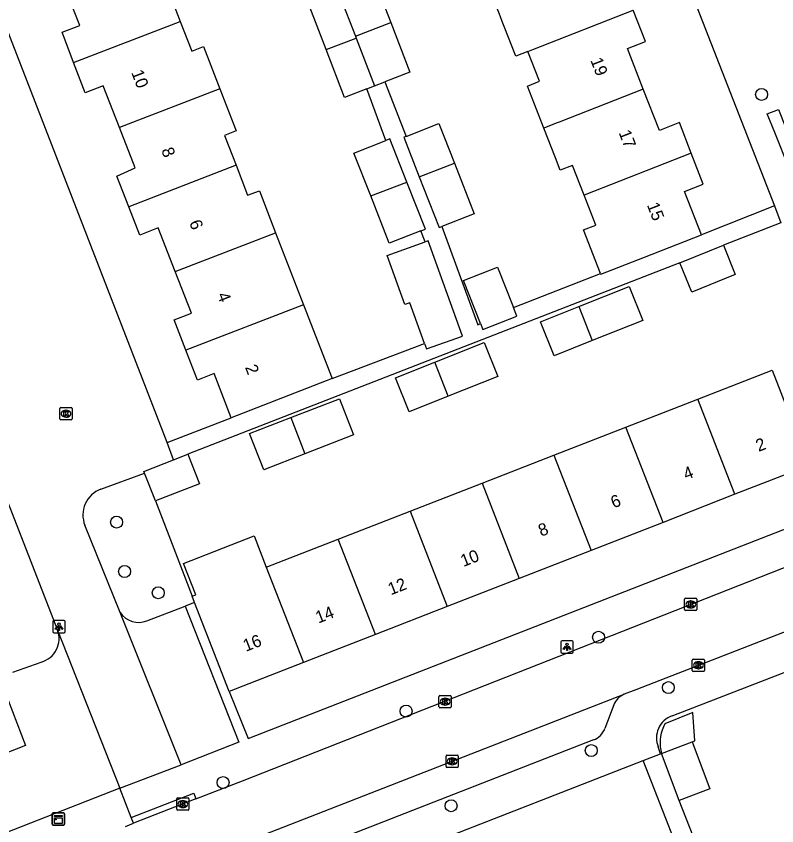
# Model space of a CAD drawing. Extents: x 159689 to 160786, y 387323 to 388339.
# Drawn here: x 160207.9 to 160270, y 387538.8 to 387604.9 of the extents above; entities that cross this region are included whole.
import ezdxf

# ---------------------------------------------------------------- set-up
doc = ezdxf.new("R2010")
doc.units = 0
for name, color, linetype in [('IMGEO_Boom', 7, 'Continuous'), ('IMGEO_Groenvoorziening', 7, 'Continuous'), ('IMGEO_Kast', 7, 'Continuous'), ('IMGEO_Kolk', 7, 'Continuous'), ('IMGEO_Lichtpunt', 7, 'Continuous'), ('IMGEO_Pand', 7, 'Continuous'), ('IMGEO_Pand_nummerreeks', 7, 'Continuous'), ('IMGEO_Parkeervlak_open', 7, 'Continuous'), ('IMGEO_Rijbaan_lokaal_open', 7, 'Continuous'), ('IMGEO_Voetpad_open', 7, 'Continuous')]:
    doc.layers.add(name, color=color, linetype=linetype)

msp = doc.modelspace()

# ---------------------------------------------------------------- linework, layer by layer
at = {"layer": 'IMGEO_Boom'}
for centre in [(160268.735, 387598.473), (160216.098, 387563.567), (160216.751, 387559.535), (160219.498, 387557.799), (160255.428, 387554.165), (160261.122, 387550.056), (160239.725, 387548.138), (160254.834, 387544.919), (160224.786, 387542.31), (160243.394, 387540.419)]:
    msp.add_circle(centre, 0.489, dxfattribs=at)
at = {"layer": 'IMGEO_Groenvoorziening'}
msp.add_lwpolyline([(160219.269, 387565.292), (160222.251, 387557.517)], dxfattribs=at)
at = {"layer": 'IMGEO_Kast'}
for p, q in [((160210.922, 387539.827), (160211.763, 387539.827)), ((160211.763, 387539.827), (160210.922, 387539.827)), ((160210.847, 387538.902), (160210.847, 387539.743)), ((160210.847, 387539.743), (160210.847, 387538.902)), ((160211.847, 387539.752), (160211.847, 387538.911)), ((160211.847, 387538.911), (160211.847, 387539.752)), ((160211.772, 387538.827), (160210.931, 387538.827)), ((160210.931, 387538.827), (160211.772, 387538.827))]:
    msp.add_line(p, q, dxfattribs=at)
for points in [[(160211.042, 387539.617), (160211.642, 387539.617), (160211.642, 387539.532), (160211.042, 387539.532), (160211.042, 387539.617)], [(160211.042, 387539.442), (160211.642, 387539.442), (160211.642, 387538.953), (160211.042, 387538.953), (160211.042, 387539.442)]]:
    msp.add_lwpolyline(points, dxfattribs=at)
msp.add_circle((160211.126, 387539.291), 0.0377, dxfattribs=at)
for centre, start, end in [((160210.925, 387539.749), 92.4484, 184.28452), ((160210.925, 387539.749), 92.4484, 184.28452), ((160211.769, 387539.749), 2.4484, 94.28452), ((160211.769, 387539.749), 2.4484, 94.28452), ((160210.925, 387538.905), 182.4484, 274.28452), ((160210.925, 387538.905), 182.4484, 274.28452), ((160211.769, 387538.905), 272.4484, 4.28452), ((160211.769, 387538.905), 272.4484, 4.28452)]:
    msp.add_arc(centre, 0.0779, start, end, dxfattribs=at)
at = {"layer": 'IMGEO_Kolk'}
for p, q in [((160211.54, 387572.916), (160212.392, 387572.916)), ((160211.465, 387571.99), (160211.465, 387572.842)), ((160211.953, 387572.696), (160211.978, 387572.696)), ((160212.466, 387572.842), (160212.466, 387571.99)), ((160212.392, 387571.916), (160211.54, 387571.916)), ((160211.976, 387572.136), (160211.951, 387572.136)), ((160262.451, 387556.425), (160262.451, 387557.277)), ((160262.526, 387557.351), (160263.378, 387557.351)), ((160262.939, 387557.131), (160262.964, 387557.131)), ((160263.452, 387557.277), (160263.452, 387556.425)), ((160263.378, 387556.351), (160262.526, 387556.351)), ((160262.962, 387556.571), (160262.937, 387556.571)), ((160263.153, 387552.381), (160264.005, 387552.381)), ((160263.078, 387551.455), (160263.078, 387552.307)), ((160263.566, 387552.161), (160263.591, 387552.161)), ((160264.079, 387552.307), (160264.079, 387551.455)), ((160264.005, 387551.381), (160263.153, 387551.381)), ((160263.589, 387551.601), (160263.564, 387551.601)), ((160242.406, 387548.483), (160242.406, 387549.335)), ((160242.481, 387549.409), (160243.333, 387549.409)), ((160242.894, 387549.189), (160242.919, 387549.189)), ((160243.407, 387549.335), (160243.407, 387548.483)), ((160243.333, 387548.409), (160242.481, 387548.409)), ((160242.917, 387548.629), (160242.892, 387548.629)), ((160242.978, 387543.615), (160242.978, 387544.467)), ((160243.053, 387544.541), (160243.905, 387544.541)), ((160243.979, 387544.467), (160243.979, 387543.615)), ((160243.466, 387544.321), (160243.491, 387544.321)), ((160243.905, 387543.541), (160243.053, 387543.541)), ((160243.489, 387543.761), (160243.464, 387543.761)), ((160221.001, 387540.128), (160221.001, 387540.98)), ((160221.076, 387541.054), (160221.928, 387541.054)), ((160221.489, 387540.834), (160221.514, 387540.834)), ((160222.002, 387540.98), (160222.002, 387540.128)), ((160221.928, 387540.054), (160221.076, 387540.054)), ((160221.512, 387540.274), (160221.487, 387540.274))]:
    msp.add_line(p, q, dxfattribs=at)
for points in [[(160211.54, 387572.916), (160212.392, 387572.916)], [(160211.465, 387571.99), (160211.465, 387572.842)], [(160211.786, 387572.616), (160211.909, 387572.616), (160211.909, 387572.465), (160212.039, 387572.616), (160212.203, 387572.616), (160212.057, 387572.465), (160212.21, 387572.216), (160212.058, 387572.216), (160211.973, 387572.38), (160211.909, 387572.313), (160211.909, 387572.216), (160211.786, 387572.216), (160211.786, 387572.616)], [(160212.466, 387572.842), (160212.466, 387571.99)], [(160212.392, 387571.916), (160211.54, 387571.916)], [(160262.451, 387556.425), (160262.451, 387557.277)], [(160262.526, 387557.351), (160263.378, 387557.351)], [(160262.772, 387557.051), (160262.895, 387557.051), (160262.895, 387556.9), (160263.025, 387557.051), (160263.189, 387557.051), (160263.043, 387556.9), (160263.196, 387556.651), (160263.044, 387556.651), (160262.959, 387556.815), (160262.895, 387556.748), (160262.895, 387556.651), (160262.772, 387556.651), (160262.772, 387557.051)], [(160263.452, 387557.277), (160263.452, 387556.425)], [(160263.378, 387556.351), (160262.526, 387556.351)], [(160263.153, 387552.381), (160264.005, 387552.381)], [(160263.078, 387551.455), (160263.078, 387552.307)], [(160263.399, 387552.081), (160263.522, 387552.081), (160263.522, 387551.93), (160263.652, 387552.081), (160263.816, 387552.081), (160263.67, 387551.93), (160263.823, 387551.681), (160263.671, 387551.681), (160263.586, 387551.845), (160263.522, 387551.778), (160263.522, 387551.681), (160263.399, 387551.681), (160263.399, 387552.081)], [(160264.079, 387552.307), (160264.079, 387551.455)], [(160264.005, 387551.381), (160263.153, 387551.381)], [(160242.406, 387548.483), (160242.406, 387549.335)], [(160242.481, 387549.409), (160243.333, 387549.409)], [(160242.727, 387549.109), (160242.85, 387549.109), (160242.85, 387548.958), (160242.98, 387549.109), (160243.144, 387549.109), (160242.998, 387548.958), (160243.151, 387548.709), (160242.999, 387548.709), (160242.914, 387548.873), (160242.85, 387548.806), (160242.85, 387548.709), (160242.727, 387548.709), (160242.727, 387549.109)], [(160243.407, 387549.335), (160243.407, 387548.483)], [(160243.333, 387548.409), (160242.481, 387548.409)], [(160242.978, 387543.615), (160242.978, 387544.467)], [(160243.053, 387544.541), (160243.905, 387544.541)], [(160243.979, 387544.467), (160243.979, 387543.615)], [(160243.299, 387544.241), (160243.422, 387544.241), (160243.422, 387544.09), (160243.552, 387544.241), (160243.716, 387544.241), (160243.57, 387544.09), (160243.723, 387543.841), (160243.571, 387543.841), (160243.486, 387544.005), (160243.422, 387543.938), (160243.422, 387543.841), (160243.299, 387543.841), (160243.299, 387544.241)], [(160243.905, 387543.541), (160243.053, 387543.541)], [(160221.001, 387540.128), (160221.001, 387540.98)], [(160221.076, 387541.054), (160221.928, 387541.054)], [(160221.322, 387540.754), (160221.445, 387540.754), (160221.445, 387540.603), (160221.575, 387540.754), (160221.739, 387540.754), (160221.593, 387540.603), (160221.746, 387540.354), (160221.594, 387540.354), (160221.509, 387540.518), (160221.445, 387540.451), (160221.445, 387540.354), (160221.322, 387540.354), (160221.322, 387540.754)], [(160222.002, 387540.98), (160222.002, 387540.128)], [(160221.928, 387540.054), (160221.076, 387540.054)]]:
    msp.add_lwpolyline(points, dxfattribs=at)
for centre, start, end in [((160211.542, 387572.84), 91.55205, 178.44795), ((160211.542, 387572.84), 91.55205, 178.44795), ((160212.39, 387572.84), 1.55205, 88.44795), ((160212.39, 387572.84), 1.55205, 88.44795), ((160211.542, 387571.992), 181.55205, 268.44795), ((160211.542, 387571.992), 181.55205, 268.44795), ((160212.39, 387571.992), 271.55205, 358.44795), ((160212.39, 387571.992), 271.55205, 358.44795), ((160262.528, 387557.275), 91.55205, 178.44795), ((160262.528, 387557.275), 91.55205, 178.44795), ((160263.376, 387557.275), 1.55205, 88.44795), ((160263.376, 387557.275), 1.55205, 88.44795), ((160262.528, 387556.427), 181.55205, 268.44795), ((160262.528, 387556.427), 181.55205, 268.44795), ((160263.376, 387556.427), 271.55205, 358.44795), ((160263.376, 387556.427), 271.55205, 358.44795), ((160263.155, 387552.305), 91.55205, 178.44795), ((160263.155, 387552.305), 91.55205, 178.44795), ((160264.003, 387552.305), 1.55205, 88.44795), ((160264.003, 387552.305), 1.55205, 88.44795), ((160263.155, 387551.457), 181.55205, 268.44795), ((160263.155, 387551.457), 181.55205, 268.44795), ((160264.003, 387551.457), 271.55205, 358.44795), ((160264.003, 387551.457), 271.55205, 358.44795), ((160242.483, 387549.333), 91.55205, 178.44795), ((160242.483, 387549.333), 91.55205, 178.44795), ((160243.331, 387549.333), 1.55205, 88.44795), ((160243.331, 387549.333), 1.55205, 88.44795), ((160242.483, 387548.485), 181.55205, 268.44795), ((160242.483, 387548.485), 181.55205, 268.44795), ((160243.331, 387548.485), 271.55205, 358.44795), ((160243.331, 387548.485), 271.55205, 358.44795), ((160243.055, 387544.465), 91.55205, 178.44795), ((160243.055, 387544.465), 91.55205, 178.44795), ((160243.903, 387544.465), 1.55205, 88.44795), ((160243.903, 387544.465), 1.55205, 88.44795), ((160243.055, 387543.617), 181.55205, 268.44795), ((160243.055, 387543.617), 181.55205, 268.44795), ((160243.903, 387543.617), 271.55205, 358.44795), ((160243.903, 387543.617), 271.55205, 358.44795), ((160221.078, 387540.978), 91.55205, 178.44795), ((160221.078, 387540.978), 91.55205, 178.44795), ((160221.926, 387540.978), 1.55205, 88.44795), ((160221.926, 387540.978), 1.55205, 88.44795), ((160221.078, 387540.13), 181.55205, 268.44795), ((160221.078, 387540.13), 181.55205, 268.44795), ((160221.926, 387540.13), 271.55205, 358.44795), ((160221.926, 387540.13), 271.55205, 358.44795)]:
    msp.add_arc(centre, 0.0765, start, end, dxfattribs=at)
for centre, major_axis, ratio, start_param, end_param in [((160211.952, 387572.416), (-0.387, 0.002), 0.722429, 4.712389, 7.853982), ((160211.977, 387572.416), (-0.39, 0.002), 0.717154, 1.570796, 4.712389), ((160262.938, 387556.851), (-0.387, 0.002), 0.722429, 4.712389, 7.853982), ((160262.963, 387556.851), (-0.39, 0.002), 0.717154, 1.570796, 4.712389), ((160263.565, 387551.881), (-0.387, 0.002), 0.722429, 4.712389, 7.853982), ((160263.59, 387551.881), (-0.39, 0.002), 0.717154, 1.570796, 4.712389), ((160242.893, 387548.909), (-0.387, 0.002), 0.722429, 4.712389, 7.853982), ((160242.918, 387548.909), (-0.39, 0.002), 0.717154, 1.570796, 4.712389), ((160243.465, 387544.041), (-0.387, 0.002), 0.722429, 4.712389, 7.853982), ((160243.49, 387544.041), (-0.39, 0.002), 0.717154, 1.570796, 4.712389), ((160221.488, 387540.554), (-0.387, 0.002), 0.722429, 4.712389, 7.853982), ((160221.513, 387540.554), (-0.39, 0.002), 0.717154, 1.570796, 4.712389)]:
    msp.add_ellipse(centre, major_axis=major_axis, ratio=ratio, start_param=start_param, end_param=end_param, dxfattribs=at)
at = {"layer": 'IMGEO_Lichtpunt'}
for p, q in [((160210.906, 387555.438), (160210.906, 387554.631)), ((160210.906, 387555.438), (160210.906, 387554.631)), ((160211.808, 387555.533), (160211, 387555.533)), ((160211.808, 387555.533), (160211, 387555.533)), ((160211.902, 387554.631), (160211.902, 387555.438)), ((160211.902, 387554.631), (160211.902, 387555.438)), ((160211, 387554.537), (160211.808, 387554.537)), ((160211, 387554.537), (160211.808, 387554.537)), ((160252.362, 387553.781), (160252.362, 387552.974)), ((160252.362, 387553.781), (160252.362, 387552.974)), ((160253.264, 387553.876), (160252.456, 387553.876)), ((160253.264, 387553.876), (160252.456, 387553.876)), ((160253.358, 387552.974), (160253.358, 387553.781)), ((160253.358, 387552.974), (160253.358, 387553.781)), ((160252.456, 387552.88), (160253.264, 387552.88)), ((160252.456, 387552.88), (160253.264, 387552.88))]:
    msp.add_line(p, q, dxfattribs=at)
for points in [[(160211.28, 387555.102), (160211.319, 387555.074), (160211.131, 387554.812), (160211.093, 387554.839), (160211.28, 387555.102)], [(160211.382, 387555.054), (160211.429, 387555.054), (160211.429, 387554.732), (160211.382, 387554.732), (160211.382, 387555.054)], [(160211.492, 387555.074), (160211.53, 387555.101), (160211.717, 387554.839), (160211.678, 387554.811), (160211.492, 387555.074)], [(160252.736, 387553.445), (160252.775, 387553.417), (160252.587, 387553.155), (160252.549, 387553.182), (160252.736, 387553.445)], [(160252.838, 387553.397), (160252.885, 387553.397), (160252.885, 387553.075), (160252.838, 387553.075), (160252.838, 387553.397)], [(160252.948, 387553.417), (160252.986, 387553.444), (160253.173, 387553.182), (160253.134, 387553.154), (160252.948, 387553.417)]]:
    msp.add_lwpolyline(points, dxfattribs=at)
for centre in [(160211.405, 387555.236), (160252.861, 387553.579)]:
    msp.add_circle(centre, 0.0994, dxfattribs=at)
for centre, start, end in [((160211, 387555.438), 90, 180), ((160211, 387555.438), 90, 180), ((160211.808, 387555.438), 0, 90), ((160211.808, 387555.438), 0, 90), ((160211, 387554.631), 180, 270), ((160211, 387554.631), 180, 270), ((160211.808, 387554.631), 270, 0), ((160211.808, 387554.631), 270, 360), ((160252.456, 387553.781), 90, 180), ((160252.456, 387553.781), 90, 180), ((160253.264, 387553.781), 0, 90), ((160253.264, 387553.781), 0, 90), ((160252.456, 387552.974), 180, 270), ((160252.456, 387552.974), 180, 270), ((160253.264, 387552.974), 270, 0), ((160253.264, 387552.974), 270, 360)]:
    msp.add_arc(centre, 0.0946, start, end, dxfattribs=at)
at = {"layer": 'IMGEO_Pand'}
for points in [[(160219.977, 387610.686), (160221.312, 387607.236), (160220.355, 387606.865), (160221.294, 387604.441)], [(160212.588, 387601.074), (160211.65, 387603.553), (160213.099, 387604.113), (160211.764, 387607.509)], [(160234.938, 387606.76), (160237.207, 387607.629), (160238.465, 387604.346)], [(160249.66, 387601.985), (160248.671, 387601.598), (160247.721, 387604.031), (160247.571, 387604.417), (160247.42, 387604.804), (160247.333, 387605.026), (160246.38, 387607.467)], [(160233.193, 387602.139), (160231.873, 387605.586), (160233.542, 387606.225)], [(160234.313, 387606.52), (160235.588, 387603.22)], [(160249.66, 387601.985), (160250.077, 387602.148), (160258.259, 387605.351)], [(160259.079, 387598.907), (160257.782, 387602.214), (160259.26, 387602.792), (160258.259, 387605.351)], [(160212.588, 387601.074), (160221.294, 387604.441)], [(160221.294, 387604.441), (160222.234, 387602.012), (160223.191, 387602.383), (160224.526, 387598.936)], [(160235.588, 387603.22), (160238.465, 387604.346)], [(160238.465, 387604.346), (160240.022, 387600.28), (160237.988, 387599.501)], [(160233.193, 387602.139), (160235.648, 387603.067)], [(160235.588, 387603.22), (160235.648, 387603.067)], [(160235.648, 387603.067), (160237.149, 387599.18)], [(160236.507, 387598.934), (160234.687, 387598.237), (160233.193, 387602.139)], [(160250.961, 387595.729), (160250.009, 387598.168), (160249.621, 387599.162), (160250.613, 387599.55), (160249.66, 387601.985)], [(160216.329, 387595.766), (160215, 387599.184), (160213.521, 387598.61), (160212.588, 387601.074)], [(160237.149, 387599.18), (160237.988, 387599.501)], [(160224.526, 387598.936), (160216.329, 387595.766)], [(160224.526, 387598.936), (160225.854, 387595.504), (160224.898, 387595.134), (160225.843, 387592.691)], [(160236.507, 387598.934), (160237.149, 387599.18)], [(160259.079, 387598.907), (160252.208, 387596.217), (160251.956, 387596.118), (160250.961, 387595.729)], [(160262.996, 387593.675), (160262.025, 387596.173), (160260.4, 387595.541), (160259.079, 387598.907)], [(160239.734, 387595.053), (160242.39, 387596.096), (160243.658, 387592.87)], [(160217.093, 387589.307), (160216.128, 387591.792), (160217.602, 387592.494), (160216.329, 387595.766)], [(160254.252, 387590.252), (160253.299, 387592.687), (160252.301, 387592.296), (160251.912, 387593.291), (160250.961, 387595.729)], [(160236.836, 387590.185), (160235.459, 387593.69), (160238.076, 387594.718)], [(160239.782, 387591.326), (160238.4, 387594.845), (160238.076, 387594.718)], [(160239.734, 387595.053), (160239.532, 387594.974), (160240.798, 387591.75)], [(160262.996, 387593.675), (160254.252, 387590.252)], [(160263.835, 387587.007), (160262.453, 387590.563), (160263.976, 387591.155), (160262.996, 387593.675)], [(160225.843, 387592.691), (160217.093, 387589.307)], [(160225.843, 387592.691), (160226.789, 387590.249), (160227.745, 387590.619), (160229.074, 387587.185)], [(160240.798, 387591.75), (160243.658, 387592.87)], [(160243.658, 387592.87), (160245.283, 387588.732), (160242.627, 387587.689)], [(160240.798, 387591.75), (160242.424, 387587.609), (160242.627, 387587.689)], [(160236.836, 387590.185), (160239.782, 387591.326)], [(160240.933, 387587.339), (160241.293, 387587.48), (160239.782, 387591.326)], [(160240.933, 387587.339), (160238.352, 387586.325), (160236.836, 387590.185)], [(160255.596, 387583.852), (160254.203, 387587.42), (160255.207, 387587.812), (160254.252, 387590.252)], [(160220.888, 387584.019), (160219.502, 387587.588), (160217.989, 387587.001), (160217.093, 387589.307)], [(160220.888, 387584.019), (160229.074, 387587.185)], [(160229.074, 387587.185), (160231.348, 387581.31)], [(160255.596, 387583.852), (160255.612, 387583.811), (160259.175, 387585.196), (160263.835, 387587.007)], [(160241.225, 387578.134), (160240.03, 387581.476), (160239.607, 387581.325), (160238.174, 387585.333), (160241.282, 387586.444)], [(160241.225, 387578.134), (160241.381, 387577.698), (160244.311, 387578.745), (160241.528, 387586.532), (160241.282, 387586.444)], [(160265.614, 387586.174), (160266.588, 387583.774), (160263.039, 387582.334), (160262.065, 387584.734)], [(160262.065, 387584.734), (160265.614, 387586.174)], [(160245.795, 387579.765), (160244.415, 387583.298), (160247.19, 387584.382), (160248.481, 387581.076)], [(160221.759, 387577.602), (160220.796, 387580.083), (160222.204, 387580.629), (160220.888, 387584.019)], [(160253.823, 387581.167), (160257.923, 387582.8), (160259.03, 387580.022), (160254.909, 387578.381)], [(160231.348, 387581.31), (160221.759, 387577.602)], [(160231.348, 387581.31), (160233.683, 387575.279)], [(160245.795, 387579.765), (160245.978, 387579.296), (160248.753, 387580.38), (160248.481, 387581.076)], [(160254.909, 387578.381), (160251.806, 387577.145), (160250.7, 387579.923), (160253.823, 387581.167)], [(160253.823, 387581.167), (160254.909, 387578.381)], [(160242.069, 387576.625), (160246.092, 387578.227), (160247.199, 387575.449), (160243.156, 387573.839)], [(160225.454, 387572.084), (160224.056, 387575.684), (160222.707, 387575.16), (160221.759, 387577.602)], [(160243.156, 387573.839), (160239.975, 387572.572), (160238.868, 387575.35), (160242.069, 387576.625)], [(160243.156, 387573.839), (160242.069, 387576.625)], [(160263.527, 387573.613), (160269.589, 387575.977), (160272.622, 387568.199), (160266.56, 387565.835)], [(160233.683, 387575.279), (160230.116, 387573.894), (160225.454, 387572.084)], [(160230.309, 387572.097), (160234.279, 387573.639), (160235.43, 387570.677), (160231.463, 387569.136)], [(160257.659, 387571.325), (160263.527, 387573.613)], [(160266.56, 387565.835), (160263.527, 387573.613)], [(160231.463, 387569.136), (160228.104, 387567.83), (160226.953, 387570.793), (160230.309, 387572.097)], [(160230.309, 387572.097), (160231.463, 387569.136)], [(160251.789, 387569.036), (160257.659, 387571.325)], [(160260.691, 387563.546), (160257.659, 387571.325)], [(160221.918, 387569.119), (160222.866, 387566.703), (160219.269, 387565.292)], [(160220.751, 387568.661), (160221.918, 387569.119)], [(160245.92, 387566.747), (160251.789, 387569.036)], [(160251.789, 387569.036), (160254.821, 387561.257)], [(160218.375, 387567.57), (160218.321, 387567.708), (160220.751, 387568.661)], [(160219.269, 387565.292), (160218.375, 387567.57)], [(160240.05, 387564.458), (160245.92, 387566.747)], [(160245.92, 387566.747), (160248.952, 387558.969)], [(160266.56, 387565.835), (160260.691, 387563.546)], [(160234.18, 387562.169), (160240.05, 387564.458)], [(160240.05, 387564.458), (160243.082, 387556.68)], [(160260.691, 387563.546), (160254.821, 387561.257)], [(160222.251, 387557.517), (160222.553, 387557.635), (160221.556, 387560.19), (160227.314, 387562.436), (160228.311, 387559.88)], [(160228.311, 387559.88), (160234.18, 387562.169)], [(160237.213, 387554.391), (160234.18, 387562.169)], [(160254.821, 387561.257), (160248.952, 387558.969)], [(160228.311, 387559.88), (160231.344, 387552.102)], [(160248.952, 387558.969), (160243.082, 387556.68)], [(160222.453, 387556.999), (160222.251, 387557.517)], [(160225.284, 387549.739), (160222.453, 387556.999)], [(160243.082, 387556.68), (160237.213, 387554.391)], [(160237.213, 387554.391), (160231.344, 387552.102)], [(160231.344, 387552.102), (160225.284, 387549.739)], [(160206.522, 387550.874), (160208.673, 387545.338), (160204.954, 387543.893)], [(160263.076, 387545.631), (160263.29, 387545.707), (160263.113, 387548.017), (160260.846, 387547.102), (160260.721, 387546.854), (160260.618, 387546.596), (160260.538, 387546.33), (160260.482, 387546.058), (160260.45, 387545.782), (160260.442, 387545.504), (160260.459, 387545.227), (160260.501, 387544.952), (160260.565, 387544.686)], [(160260.565, 387544.686), (160263.076, 387545.631)], [(160263.076, 387545.631), (160264.519, 387541.798), (160262.008, 387540.853)], [(160262.008, 387540.853), (160260.565, 387544.686)]]:
    msp.add_lwpolyline(points, dxfattribs=at)
at = {"layer": 'IMGEO_Parkeervlak_open'}
for points in [[(160218.565, 387555.505), (160221.688, 387556.705)], [(160207.64, 387551.308), (160209.952, 387552.144)]]:
    msp.add_lwpolyline(points, dxfattribs=at)
for centre, radius, start, end in [((160217.906, 387557.255), 1.87, 215.2827, 290.63712), ((160209.408, 387554.061), 1.993, 285.84022, 20.31162)]:
    msp.add_arc(centre, radius, start, end, dxfattribs=at)
at = {"layer": 'IMGEO_Rijbaan_lokaal_open'}
for points in [[(160220.212, 387570.053), (160197.996, 387627.397)], [(160188.988, 387612.056), (160211.277, 387554.753)], [(160220.751, 387568.661), (160220.212, 387570.053)], [(160214.817, 387566.257), (160218.375, 387567.57)], [(160216.379, 387556.175), (160213.509, 387563.306)], [(160222.572, 387540.974), (160226.363, 387542.456), (160272.049, 387560.443), (160272.476, 387560.614), (160277.48, 387562.534), (160278.65, 387562.998)], [(160280.555, 387558.375), (160279.081, 387557.799), (160273.19, 387555.588), (160272.41, 387555.286), (160258.478, 387549.884), (160257.52, 387549.51)], [(160221.377, 387543.755), (160216.379, 387556.175)], [(160211.277, 387554.753), (160216.374, 387541.845)], [(160218.546, 387534.325), (160221.046, 387535.303), (160257.52, 387549.51)], [(160216.374, 387541.845), (160221.377, 387543.755)], [(160222.572, 387540.974), (160217.479, 387538.983)], [(160216.827, 387538.728), (160217.479, 387538.983)]]:
    msp.add_lwpolyline(points, dxfattribs=at)
msp.add_arc((160215.598, 387564.145), 2.252, 110.30451, 201.88585, dxfattribs=at)
at = {"layer": 'IMGEO_Voetpad_open'}
for points in [[(160246.773, 387648.334), (160269.778, 387589.373)], [(160237.988, 387599.501), (160239.734, 387595.053)], [(160238.076, 387594.718), (160236.507, 387598.934)], [(160270.124, 387597.246), (160271.869, 387592.79), (160270.98, 387592.426), (160269.826, 387595.362), (160269.193, 387596.881), (160270.124, 387597.246)], [(160269.778, 387589.373), (160263.835, 387587.007)], [(160269.778, 387589.373), (160270.311, 387588.007)], [(160242.627, 387587.689), (160245.567, 387579.681), (160245.795, 387579.765)], [(160270.311, 387588.007), (160265.614, 387586.174)], [(160241.282, 387586.444), (160240.933, 387587.339)], [(160262.065, 387584.734), (160221.918, 387569.119)], [(160248.481, 387581.076), (160255.596, 387583.852)], [(160233.683, 387575.279), (160241.225, 387578.134)], [(160220.212, 387570.053), (160225.454, 387572.084)], [(160225.284, 387549.739), (160226.828, 387545.911), (160277.166, 387565.55)], [(160222.453, 387556.999), (160221.688, 387556.705)], [(160221.688, 387556.705), (160226.074, 387545.613), (160221.377, 387543.755)], [(160261.425, 387547.75), (160280.969, 387555.305)], [(160256.662, 387548.641), (160255.94, 387546.713)], [(160255.023, 387545.783), (160221.98, 387532.911), (160219.479, 387531.933)], [(160260.495, 387544.659), (160260.298, 387545.217)], [(160259.073, 387544.104), (160260.495, 387544.659)], [(160260.565, 387544.686), (160260.495, 387544.659)], [(160205.916, 387523.37), (160259.073, 387544.104)], [(160261.594, 387537.642), (160259.073, 387544.104)], [(160216.374, 387541.845), (160194.339, 387533.238)], [(160217.295, 387539.447), (160216.374, 387541.845)], [(160217.295, 387539.447), (160222.388, 387541.438), (160222.572, 387540.974)], [(160275.412, 387506.704), (160262.008, 387540.853)], [(160217.479, 387538.983), (160217.295, 387539.447)]]:
    msp.add_lwpolyline(points, dxfattribs=at)
for centre, radius, start, end in [((160258.148, 387548.032), 1.606, 113.02559, 157.70428), ((160262.066, 387545.948), 1.913, 109.57168, 202.45718), ((160254.444, 387547.271), 1.597, 291.26027, 339.54626)]:
    msp.add_arc(centre, radius, start, end, dxfattribs=at)

# ---------------------------------------------------------------- texts
at = {"layer": 'IMGEO_Pand_nummerreeks'}
for s, rotation, p in [('19', 291.33674, (160254.745, 387601.267)), ('10', 291.10183, (160217.277, 387600.27)), ('17', 291.33674, (160257.052, 387595.36)), ('8', 291.10183, (160219.725, 387593.931)), ('15', 291.33674, (160259.359, 387589.453)), ('6', 291.10183, (160222.004, 387588.024)), ('4', 291.10257, (160224.284, 387582.114)), ('2', 291.10257, (160226.564, 387576.205)), ('2', 21.30387, (160268.489, 387569.292)), ('4', 21.30387, (160262.574, 387566.986)), ('6', 21.30387, (160256.656, 387564.678)), ('8', 21.30387, (160250.743, 387562.372)), ('10', 21.30387, (160244.397, 387559.897)), ('12', 21.30387, (160238.474, 387557.588)), ('14', 21.30387, (160232.559, 387555.281)), ('16', 21.30257, (160226.642, 387552.973))]:
    msp.add_text(s, height=1, rotation=rotation, dxfattribs=at).set_placement(p)

doc.saveas('drawing.dxf')
